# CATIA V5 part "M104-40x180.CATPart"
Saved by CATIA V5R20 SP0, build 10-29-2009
Part number: M104-40x180
Source: Unknown
Bounding box of the stored display mesh (mm): x -19.994 to 19.994, y -19.994 to 19.994, z 0 to 180
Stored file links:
  C:\Users\Utente\Desktop\IO LAVORO\3D X SITO CF\X SITO\M104\M104-40x180.CATPart

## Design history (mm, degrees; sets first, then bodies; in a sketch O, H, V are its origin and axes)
Body1 (main body)
  Solid1 "PartBody": solid without history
